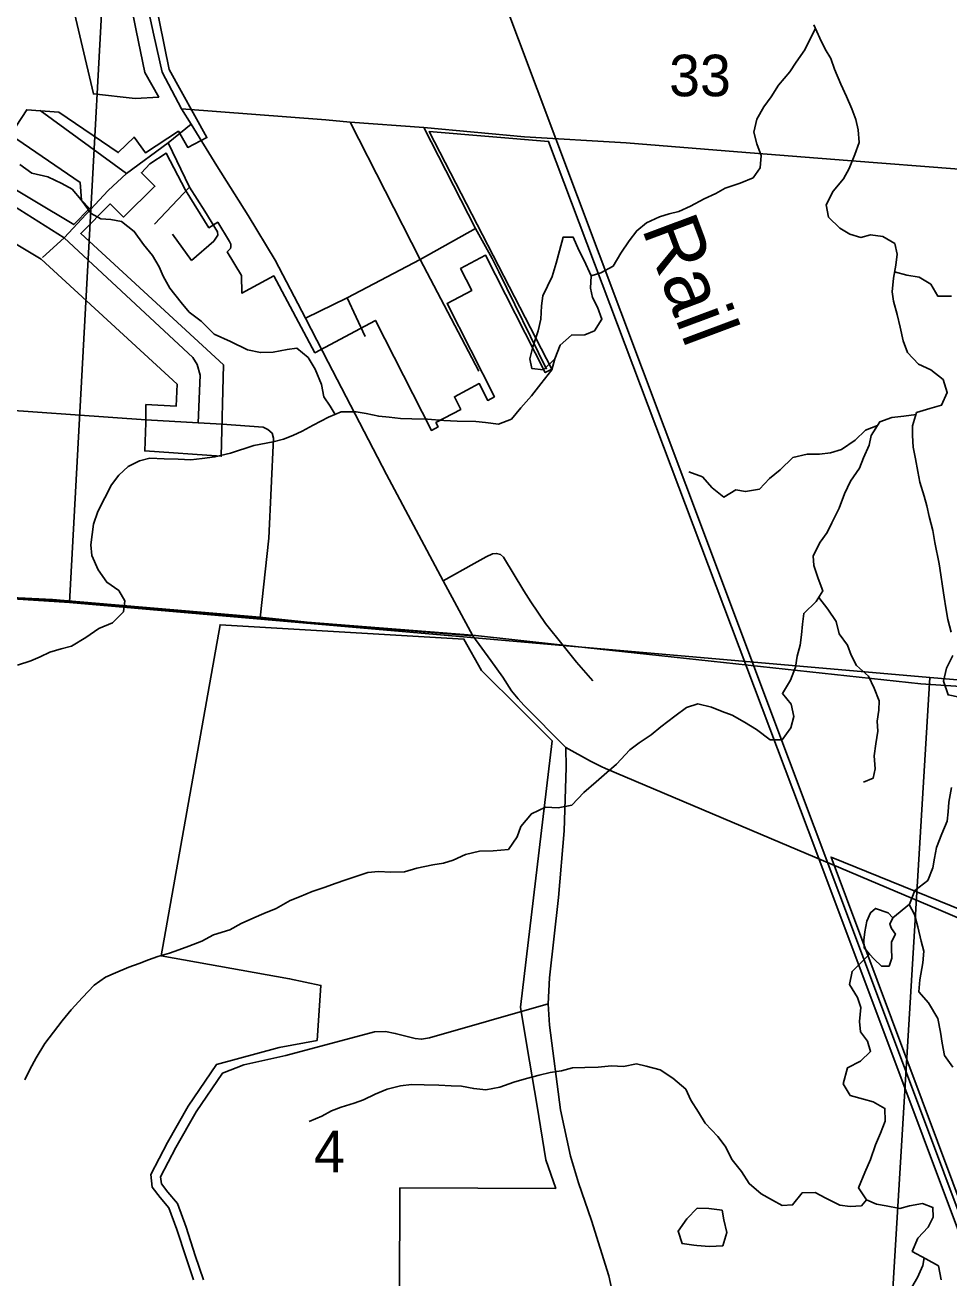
# Model space of a CAD drawing. Extents: x 0 to 34, y 0 to 22.
# Drawn here: x 28.447 to 29.378, y 19.082 to 20.344 of the extents above; entities that cross this region are included whole.
import ezdxf

# ---------------------------------------------------------------- set-up
doc = ezdxf.new("R2010")
doc.units = 0
for name, color, linetype in [('GM_X_City_Street', 7, 'Continuous'), ('GM_X_Corporation', 7, 'Continuous'), ('GM_X_County_Road', 7, 'Continuous'), ('GM_X_Major_River', 7, 'Continuous'), ('GM_X_Minor_Lake', 7, 'Continuous'), ('GM_X_Minor_River', 7, 'Continuous'), ('GM_X_Rail_Line', 7, 'Continuous'), ('GM_X_Rail_Line_Text', 7, 'Continuous'), ('GM_X_Section_Text', 7, 'Continuous'), ('GM_X_State_Route', 7, 'Continuous'), ('GM_X_Township_Road', 7, 'Continuous')]:
    doc.layers.add(name, color=color, linetype=linetype)

msp = doc.modelspace()

# ---------------------------------------------------------------- linework, layer by layer
at = {"layer": 'GM_X_City_Street'}
msp.add_line((28.5492, 20.1947), (28.4619, 20.2581), dxfattribs=at)
for points in [[(28.95, 20.2316), (29.0526, 20.2256), (29.1647, 20.2167), (29.2757, 20.2079), (29.3882, 20.1992), (29.48, 20.1917), (29.5875, 20.1831), (29.6516, 20.1783), (29.6584, 20.1781), (29.6681, 20.179), (29.6791, 20.1815), (29.6912, 20.1852), (29.7063, 20.1906), (29.722, 20.1978), (29.7365, 20.205), (29.7592, 20.2196), (29.858, 20.3004), (29.8857, 20.3208), (29.9177, 20.3417)], [(28.6046, 20.2598), (28.75, 20.2489), (28.7745, 20.2466), (28.8485, 20.2411), (28.95, 20.2316)], [(28.4643, 20.1103), (28.4861, 20.1301), (28.5307, 20.1776), (28.5492, 20.1947), (28.5909, 20.2256), (28.6141, 20.2445)], [(28.6211, 19.9437), (28.6231, 19.9918), (28.6203, 20.0024), (28.616, 20.0095), (28.4861, 20.1301), (28.4414, 20.1581), (28.3821, 20.195), (28.3757, 20.1985), (28.3672, 20.2006), (28.3594, 20.2017), (28.3263, 20.2006), (28.2805, 20.1982), (28.2717, 20.1938), (28.2616, 20.1834)], [(28.5684, 19.9468), (28.6211, 19.9437), (28.6455, 19.9423)], [(28.6265, 19.0804), (28.6183, 19.1051), (28.609, 19.1336), (28.6004, 19.1572), (28.5906, 19.1686), (28.5842, 19.177), (28.5834, 19.1842), (28.5987, 19.2137), (28.6194, 19.2497), (28.6457, 19.2887), (28.6674, 19.297), (28.7097, 19.3065), (28.7991, 19.3301), (28.8101, 19.3304), (28.8199, 19.3287), (28.84, 19.3234), (28.8464, 19.3227), (28.8545, 19.3241), (28.9739, 19.3586)]]:
    msp.add_lwpolyline(points, dxfattribs=at)
at = {"layer": 'GM_X_Corporation'}
for points in [[(27.713, 19.8126), (27.7479, 19.8098), (27.921, 19.7976), (28.0078, 19.7898), (28.15, 19.7813), (28.3845, 19.7702), (28.4743, 19.7657), (28.6835, 19.7478), (28.7311, 19.743), (28.8977, 19.7297), (28.9889, 19.7198), (29.3495, 19.6807), (29.4353, 19.675), (29.5232, 19.6666), (30.3167, 19.5906), (30.3167, 20.9), (26.3743, 20.9)], [(28.5483, 20.5152), (28.5921, 20.2996), (28.6301, 20.2309), (28.6107, 20.221), (28.6014, 20.2373), (28.5683, 20.2156), (28.5566, 20.2315), (28.5407, 20.2158), (28.481, 20.2565), (28.4486, 20.259), (28.4322, 20.2339), (28.5023, 20.1858), (28.5036, 20.168), (28.5118, 20.1596), (28.4959, 20.1434), (28.3709, 20.2181)], [(28.5435, 20.4146), (28.5589, 20.339), (28.5675, 20.2966), (28.5816, 20.2718), (28.5577, 20.2705), (28.5157, 20.2749), (28.4908, 20.3808)], [(28.3604, 20.1698), (28.4629, 20.1086), (28.6001, 19.9826), (28.599, 19.9604), (28.5686, 19.9621), (28.5686, 19.9435), (28.5681, 19.9342), (28.5675, 19.9154), (28.6445, 19.91), (28.6468, 20.002), (28.503, 20.1343), (28.5325, 20.1642), (28.5461, 20.1509), (28.5776, 20.1819), (28.5641, 20.1955), (28.5727, 20.2045), (28.5889, 20.2153), (28.6086, 20.1781), (28.6321, 20.1401), (28.641, 20.1457), (28.6527, 20.1264), (28.6534, 20.1251), (28.654, 20.1237), (28.6543, 20.1225), (28.6542, 20.121), (28.6538, 20.1193), (28.6506, 20.1159), (28.6649, 20.0921), (28.6652, 20.0744), (28.6974, 20.0917), (28.7389, 20.0143), (28.7999, 20.0468), (28.8563, 19.9361), (28.863, 19.9396), (28.8608, 19.9439), (28.8859, 19.9572), (28.8795, 19.9699), (28.9045, 19.9832), (28.9131, 19.9663), (28.9198, 19.9699), (28.872, 20.0639), (28.8969, 20.077), (28.8857, 20.099), (28.9108, 20.1124), (28.971, 19.9942), (28.9777, 19.9978), (28.8541, 20.2372), (28.9744, 20.2272), (29.2436, 19.5128), (29.5681, 18.6478)], [(30.3167, 14.1), (30.3167, 19.5906), (29.5232, 19.6666), (29.4353, 19.675), (29.3495, 19.6807), (28.9889, 19.7198), (28.8977, 19.7297), (28.7311, 19.743), (28.6835, 19.7478), (28.4743, 19.7657), (28.3845, 19.7702), (28.15, 19.7813), (28.0078, 19.7898), (27.921, 19.7976), (27.7479, 19.8098), (27.713, 19.8126)], [(28.6165, 19.0805), (28.6091, 19.1027), (28.5998, 19.131), (28.5918, 19.1529), (28.583, 19.1632), (28.5748, 19.1739), (28.5735, 19.1866), (28.5902, 19.2188), (28.6111, 19.2552), (28.6396, 19.2974), (28.7029, 19.3145), (28.741, 19.3215), (28.745, 19.3769), (28.7133, 19.3837), (28.5841, 19.4067), (28.6433, 19.7402), (28.8891, 19.7259), (28.9068, 19.6942), (28.946, 19.6553), (28.9781, 19.6233), (28.9461, 19.3551), (28.9525, 19.3164), (28.963, 19.2554), (28.9716, 19.2012), (28.9816, 19.1725), (28.8245, 19.173), (28.8221, 18.423)], [(29.5806, 18.6469), (29.2591, 19.5062), (29.4529, 19.4276)]]:
    msp.add_lwpolyline(points, dxfattribs=at)
for points in [[(27.5018, 20.8365), (28.5465, 20.7695), (28.4917, 19.7627), (28.3876, 19.7694), (27.4311, 19.8373)], [(28.5465, 20.7695), (29.5293, 20.6826), (29.4415, 19.6802), (29.3585, 19.6871), (28.4917, 19.7627)], [(28.4917, 19.7627), (29.3585, 19.6871), (29.2972, 18.6715), (28.6566, 18.7331), (28.2889, 18.7562), (28.3876, 19.7694)], [(30.3167, 18.7853), (30.3167, 19.5984), (29.4415, 19.6802), (29.3585, 19.6871), (29.2972, 18.6715), (30.2969, 18.5954)]]:
    msp.add_lwpolyline(points, close=True, dxfattribs=at)
at = {"layer": 'GM_X_County_Road'}
msp.add_lwpolyline([(29.0546, 18.9586), (29.0544, 18.9674), (29.0538, 18.9872), (29.0494, 19.018), (29.0351, 19.0845), (29.0176, 19.1401), (29.0044, 19.1782), (28.9965, 19.2049), (28.9863, 19.2516), (28.9753, 19.3368), (28.9739, 19.3586), (28.9753, 19.3846), (28.9842, 19.4654), (28.99, 19.5328), (28.9921, 19.5966), (28.9916, 19.6165)], dxfattribs=at)
at = {"layer": 'GM_X_Major_River'}
for points in [[(29.2417, 20.3445), (29.2476, 20.3312), (29.2532, 20.3201), (29.2588, 20.3106), (29.2625, 20.2999), (29.2688, 20.2847), (29.2744, 20.2725), (29.28, 20.26), (29.2841, 20.2493), (29.2862, 20.2387), (29.2873, 20.2261), (29.283, 20.214), (29.2772, 20.2), (29.2714, 20.1895), (29.2611, 20.177), (29.2542, 20.1634), (29.2563, 20.1509), (29.268, 20.1398), (29.2778, 20.1336), (29.2891, 20.1305), (29.2986, 20.1331), (29.3111, 20.1315), (29.3232, 20.1242), (29.3257, 20.1135), (29.3241, 20.1025), (29.3218, 20.0893), (29.3205, 20.0756), (29.3219, 20.0661), (29.3256, 20.0528), (29.3285, 20.0399), (29.3318, 20.0262), (29.3359, 20.0144), (29.3472, 20.0029), (29.3596, 19.9972), (29.3721, 19.9872), (29.3761, 19.9743), (29.3703, 19.9614), (29.3585, 19.9581), (29.3452, 19.954), (29.341, 19.9408), (29.3409, 19.9309), (29.3419, 19.9191), (29.3441, 19.9073), (29.3463, 19.8948), (29.3484, 19.8838), (29.3529, 19.8697), (29.3554, 19.8602), (29.358, 19.8492), (29.3617, 19.8351), (29.3635, 19.823), (29.3678, 19.8017), (29.3696, 19.7907), (29.3714, 19.7793), (29.3729, 19.7679), (29.3747, 19.7572), (29.3768, 19.7455), (29.3801, 19.7329)], [(29.3818, 19.7094), (29.3753, 19.6965), (29.3722, 19.6833), (29.377, 19.6696), (29.3883, 19.6672)], [(29.3803, 19.5762), (29.3776, 19.5614), (29.3771, 19.5519), (29.3759, 19.5425), (29.3705, 19.5296), (29.3651, 19.516), (29.3631, 19.505), (29.3615, 19.4955), (29.3564, 19.4827), (29.3435, 19.4725), (29.338, 19.4589), (29.3213, 19.445)], [(29.3164, 19.45), (29.3039, 19.4546), (29.2986, 19.4501), (29.2951, 19.4418), (29.2931, 19.4308), (29.2919, 19.4225), (29.2922, 19.4149), (29.2978, 19.4084)], [(29.3164, 19.45), (29.3039, 19.4546), (29.2986, 19.4501), (29.2951, 19.4418), (29.2931, 19.4308), (29.2919, 19.4225), (29.2922, 19.4149), (29.2978, 19.4084), (29.3023, 19.4034), (29.3099, 19.3965), (29.3174, 19.3965), (29.3202, 19.4044), (29.3199, 19.4143), (29.3199, 19.4207), (29.3222, 19.4256), (29.3238, 19.4287), (29.32, 19.4344), (29.3182, 19.4386), (29.3213, 19.445)], [(29.3213, 19.445), (29.3164, 19.45)], [(29.2978, 19.4084), (29.3023, 19.4034), (29.3099, 19.3965), (29.3174, 19.3965), (29.3202, 19.4044), (29.3199, 19.4143), (29.3199, 19.4207), (29.3222, 19.4256), (29.3238, 19.4287), (29.32, 19.4344), (29.3182, 19.4386), (29.3213, 19.445)], [(29.2978, 19.4084), (29.2802, 19.3911), (29.2775, 19.3778), (29.2857, 19.3648), (29.289, 19.3546), (29.2878, 19.3405), (29.2885, 19.3303), (29.2956, 19.3208), (29.2989, 19.3105), (29.2886, 19.3007), (29.2756, 19.294), (29.2713, 19.2777), (29.2784, 19.2662), (29.2917, 19.2624), (29.3015, 19.2596), (29.3132, 19.2531), (29.3135, 19.2402), (29.3088, 19.2281), (29.3038, 19.2163), (29.2987, 19.2016), (29.2929, 19.1884), (29.2868, 19.1732), (29.2946, 19.161), (29.3048, 19.1568), (29.3146, 19.1548), (29.3283, 19.1524), (29.3381, 19.155), (29.351, 19.1572), (29.3616, 19.1533), (29.3619, 19.1434), (29.3569, 19.1336), (29.3466, 19.1223), (29.3408, 19.1091), (29.3544, 19.1017), (29.3672, 19.0944), (29.3701, 19.0804)]]:
    msp.add_lwpolyline(points, dxfattribs=at)
at = {"layer": 'GM_X_Minor_Lake'}
for points in [[(29.0173, 20.0918), (29.0101, 20.107), (29.0049, 20.1176), (28.9992, 20.1306), (28.989, 20.1306), (28.9852, 20.1169), (28.9821, 20.1044), (28.9779, 20.0912), (28.9733, 20.0813), (28.9684, 20.0715), (28.9672, 20.0616), (28.9664, 20.048), (28.9637, 20.0362), (28.9584, 20.0203), (28.9553, 20.0082), (28.9575, 19.9983), (28.9693, 19.9972), (28.9807, 20.0081)], [(28.9807, 20.0081), (28.986, 20.0218), (28.9974, 20.032), (29.011, 20.0323), (29.0205, 20.0364), (29.0281, 20.0482), (29.0236, 20.0603), (29.0187, 20.0698), (29.0165, 20.0793), (29.0173, 20.0918)], [(29.1492, 19.1505), (29.1359, 19.1524), (29.1242, 19.1525), (29.1136, 19.1419), (29.1048, 19.1294), (29.1089, 19.1169), (29.1207, 19.1153)], [(29.1207, 19.1153), (29.1237, 19.1149), (29.1366, 19.1141), (29.1498, 19.1148), (29.154, 19.1281), (29.151, 19.141), (29.1492, 19.1505)]]:
    msp.add_lwpolyline(points, dxfattribs=at)
at = {"layer": 'GM_X_Minor_River'}
for points in [[(29.2434, 20.3407), (29.2372, 20.3292), (29.2326, 20.3194), (29.2239, 20.3069), (29.2174, 20.2971), (29.206, 20.2838), (29.1988, 20.2721), (29.1912, 20.2619), (29.1843, 20.2494), (29.1813, 20.2365), (29.1843, 20.2247), (29.1884, 20.213), (29.1876, 20.2005), (29.1804, 20.1906), (29.1675, 20.185), (29.1523, 20.1801), (29.1428, 20.1748), (29.1311, 20.1692), (29.1174, 20.162), (29.1057, 20.1564), (29.0958, 20.1541), (29.086, 20.1511), (29.0731, 20.1451), (29.0632, 20.1372), (29.0556, 20.127), (29.0473, 20.1145), (29.0393, 20.1016), (29.0271, 20.0948), (29.0173, 20.0918), (29.0165, 20.0793), (29.0187, 20.0698), (29.0236, 20.0603), (29.0281, 20.0482), (29.0205, 20.0364), (29.011, 20.0323), (28.9974, 20.032), (28.986, 20.0218), (28.9807, 20.0081), (28.9776, 19.9971), (28.9666, 19.9831), (28.9571, 19.9707), (28.9464, 19.9589), (28.9369, 19.9472), (28.924, 19.9423), (28.9108, 19.9439), (28.901, 19.9451), (28.8821, 19.9455), (28.8688, 19.9459), (28.8522, 19.9475), (28.8366, 19.9476), (28.8253, 19.948), (28.8136, 19.9492), (28.8033, 19.9503), (28.7905, 19.953), (28.7803, 19.9546), (28.7655, 19.9546), (28.7526, 19.9494), (28.7371, 19.9414), (28.7261, 19.9354), (28.7166, 19.9309), (28.7071, 19.9271), (28.6969, 19.9245), (28.6772, 19.9208), (28.6537, 19.9131)], [(28.6538, 20.0257), (28.6375, 20.033), (28.6244, 20.046), (28.6123, 20.0552), (28.6041, 20.0647), (28.5928, 20.0792), (28.5861, 20.0914), (28.582, 20.1009), (28.5753, 20.1123), (28.5663, 20.1234), (28.5569, 20.1364), (28.5441, 20.1463), (28.5331, 20.1483), (28.5233, 20.1491), (28.5135, 20.1545), (28.5034, 20.1682), (28.4944, 20.1789), (28.4838, 20.1846), (28.4699, 20.1916), (28.4536, 20.1951), (28.4416, 20.2039)], [(29.3229, 20.0956), (29.3352, 20.0923), (29.3477, 20.0903), (29.3594, 20.0834), (29.3665, 20.0713), (29.3802, 20.0712)], [(28.7593, 19.9521), (28.7542, 19.9604), (28.7478, 19.9699), (28.7456, 19.9824), (28.7392, 19.9976), (28.732, 20.0093), (28.7207, 20.0189), (28.7109, 20.0174), (28.6968, 20.0148), (28.684, 20.0144), (28.6711, 20.0171), (28.6538, 20.0257)], [(29.3446, 19.9519), (29.3324, 19.9504), (29.3203, 19.949), (29.3082, 19.9448), (29.2994, 19.9308), (29.2975, 19.9213), (29.2918, 19.9085), (29.2876, 19.8979), (29.2785, 19.885), (29.2727, 19.8721), (29.267, 19.8577), (29.2598, 19.843), (29.2552, 19.8331), (29.248, 19.8233), (29.2411, 19.8097), (29.2415, 19.7998), (29.246, 19.7869), (29.2508, 19.7744), (29.244, 19.7638), (29.2315, 19.7517), (29.2303, 19.7407), (29.2291, 19.7301), (29.2279, 19.7198), (29.2249, 19.7085), (29.223, 19.6975), (29.218, 19.6846), (29.21, 19.671), (29.2187, 19.6603), (29.2216, 19.6478), (29.2186, 19.6364), (29.2098, 19.6243), (29.1977, 19.6244), (29.1838, 19.6347), (29.1717, 19.6423), (29.1592, 19.6492), (29.1494, 19.653), (29.1384, 19.6572), (29.1248, 19.6606), (29.1134, 19.6569), (29.1017, 19.6482), (29.0876, 19.6376), (29.0778, 19.6293), (29.0656, 19.6214), (29.0561, 19.6142), (29.0428, 19.5999), (29.033, 19.5916), (29.0223, 19.5821), (29.0098, 19.5712), (28.9977, 19.5587), (28.984, 19.5557), (28.9712, 19.5565), (28.9571, 19.5497), (28.9465, 19.5369), (28.9427, 19.5266), (28.9339, 19.5138), (28.9184, 19.5127), (28.9048, 19.5123), (28.8908, 19.509), (28.8783, 19.5033), (28.8684, 19.5), (28.8578, 19.4985), (28.8415, 19.4951), (28.829, 19.4914), (28.8154, 19.491), (28.8029, 19.4918), (28.7923, 19.4907), (28.7813, 19.487), (28.77, 19.4832), (28.7593, 19.4798), (28.7491, 19.4761), (28.7362, 19.4716), (28.7233, 19.4663), (28.7139, 19.4626), (28.6998, 19.4543), (28.6873, 19.4494), (28.6775, 19.4452), (28.6646, 19.4392), (28.653, 19.433)], [(29.3057, 19.9409), (29.2938, 19.9362), (29.2832, 19.9263), (29.2695, 19.9169), (29.2585, 19.9135), (29.2475, 19.912), (29.235, 19.9121), (29.2206, 19.9087), (29.2077, 19.8962), (29.1971, 19.8876), (29.1869, 19.877), (29.1728, 19.8744), (29.163, 19.8763), (29.1509, 19.8688), (29.1392, 19.8783), (29.1294, 19.8893), (29.1158, 19.8943)], [(28.6537, 19.9131), (28.6382, 19.9094), (28.6253, 19.9076), (28.614, 19.9065), (28.6011, 19.907), (28.5871, 19.9075), (28.5727, 19.9079), (28.5621, 19.9054), (28.5507, 19.8997), (28.5412, 19.8911), (28.534, 19.8813), (28.5271, 19.868), (28.5202, 19.8544), (28.5159, 19.8416), (28.5143, 19.8313), (28.5131, 19.8207), (28.5142, 19.8101), (28.5205, 19.7957), (28.5291, 19.7831), (28.5412, 19.7747), (28.5472, 19.7644), (28.546, 19.7534), (28.5349, 19.7421), (28.5212, 19.7365), (28.5079, 19.7275), (28.4935, 19.7188), (28.4833, 19.7159), (28.4719, 19.7125), (28.462, 19.7081), (28.4525, 19.7039), (28.4393, 19.6995)], [(29.2466, 19.7678), (29.2557, 19.7561), (29.264, 19.7436), (29.2673, 19.7311), (29.2756, 19.7197), (29.2794, 19.7098), (29.2846, 19.6992), (29.2967, 19.6885), (29.3024, 19.6763), (29.3076, 19.6638), (29.3072, 19.6543), (29.3056, 19.643), (29.306, 19.6331), (29.3041, 19.6202), (29.3025, 19.6081), (29.3036, 19.5952), (29.3013, 19.5857), (29.2918, 19.5816)], [(29.3377, 19.4586), (29.3432, 19.4483), (29.3466, 19.4361), (29.3499, 19.4217), (29.3525, 19.4115), (29.3514, 19.3997), (29.3483, 19.3827), (29.3475, 19.3705), (29.3573, 19.3595), (29.3667, 19.3435), (29.3693, 19.3299), (29.3708, 19.3189), (29.3734, 19.3064), (29.3817, 19.2946)], [(28.653, 19.433), (28.6368, 19.4281), (28.625, 19.4214), (28.6118, 19.4165), (28.6019, 19.4128), (28.5924, 19.4095), (28.5807, 19.4061), (28.5712, 19.4028), (28.5617, 19.399), (28.5515, 19.3953), (28.5378, 19.3897), (28.5279, 19.3852), (28.5165, 19.3773), (28.5047, 19.3649), (28.4933, 19.3525), (28.4841, 19.3412), (28.4669, 19.3185), (28.4581, 19.3042), (28.4516, 19.2924), (28.4466, 19.2819)], [(29.2946, 19.161), (29.2896, 19.155), (29.2782, 19.1542), (29.268, 19.1558), (29.2537, 19.1627), (29.2431, 19.1684), (29.2298, 19.168), (29.2203, 19.1559), (29.2097, 19.1552), (29.1999, 19.1606), (29.1886, 19.1671), (29.1765, 19.1773), (29.1686, 19.1895), (29.1592, 19.2013), (29.1524, 19.215), (29.1449, 19.2248), (29.1321, 19.2382), (29.1253, 19.2492), (29.1178, 19.2613), (29.1125, 19.2724), (29.0997, 19.2834), (29.0868, 19.2918), (29.0728, 19.2956), (29.063, 19.2979), (29.0497, 19.2953), (29.0376, 19.2961), (29.0244, 19.2946), (29.0108, 19.2943), (28.9983, 19.294), (28.9873, 19.291), (28.9759, 19.2891), (28.9649, 19.2865), (28.9521, 19.2831), (28.9392, 19.2794), (28.9252, 19.2745), (28.9112, 19.2719), (28.899, 19.2731), (28.8866, 19.2754), (28.8763, 19.2758), (28.8639, 19.2766), (28.8491, 19.277), (28.8362, 19.2771), (28.8253, 19.276), (28.8116, 19.2726), (28.7995, 19.2673), (28.7877, 19.2617), (28.7783, 19.2583), (28.7654, 19.2542), (28.7555, 19.2508), (28.7457, 19.2452), (28.7332, 19.2399)], [(29.3528, 19.1026), (29.3515, 19.0948), (29.3461, 19.0827), (29.3381, 19.0691)]]:
    msp.add_lwpolyline(points, dxfattribs=at)
at = {"layer": 'GM_X_Rail_Line'}
for points in [[(29.1913, 19.6716), (29.1345, 19.823), (28.9817, 20.2298), (28.8105, 20.6857), (28.73, 20.9)], [(29.4527, 18.9755), (29.2926, 19.4017), (29.1913, 19.6716)]]:
    msp.add_lwpolyline(points, dxfattribs=at)
at = {"layer": 'GM_X_State_Route'}
msp.add_line((28.5767, 20.3343), (28.5439, 20.4822), dxfattribs=at)
for points in [[(28.6402, 20.2026), (28.6141, 20.2445), (28.6046, 20.2598), (28.5851, 20.2969), (28.5767, 20.3343)], [(28.7524, 20.0048), (28.7295, 20.049), (28.699, 20.1074), (28.6715, 20.1524), (28.6402, 20.2026)], [(28.8979, 19.7292), (28.8682, 19.7846), (28.811, 19.8915), (28.7524, 20.0048)], [(28.9438, 19.6658), (28.9371, 19.6738), (28.9281, 19.6875), (28.9162, 19.7041), (28.8979, 19.7292)], [(29.0273, 19.5976), (29.0166, 19.6027), (28.9916, 19.6165), (28.9493, 19.6592), (28.9438, 19.6658)], [(29.4998, 19.3943), (29.4097, 19.4354), (29.3673, 19.4536), (29.2078, 19.5211), (29.0317, 19.5955), (29.0273, 19.5976)]]:
    msp.add_lwpolyline(points, dxfattribs=at)
at = {"layer": 'GM_X_Township_Road'}
for p, q in [((28.5771, 20.1438), (28.6126, 20.1809)), ((28.5954, 20.1338), (28.6146, 20.1073)), ((28.9723, 19.9978), (28.9242, 20.0956)), ((28.7715, 20.0697), (28.7896, 20.0305))]:
    msp.add_line(p, q, dxfattribs=at)
for points in [[(28.904, 19.9958), (28.845, 20.1083), (28.7745, 20.2466)], [(28.9242, 20.0956), (28.9174, 20.1093), (28.9008, 20.1393), (28.8485, 20.2411)], [(28.6278, 20.1568), (28.6126, 20.1809), (28.5909, 20.2256)], [(28.6146, 20.1073), (28.6372, 20.1267), (28.6412, 20.1326), (28.6408, 20.1359), (28.6278, 20.1568)], [(28.7295, 20.049), (28.7715, 20.0697), (28.845, 20.1083), (28.9008, 20.1393)], [(28.5684, 19.9468), (28.3877, 19.9595), (28.2855, 19.9623)], [(28.6838, 19.7473), (28.6925, 19.8276), (28.6972, 19.9281), (28.6958, 19.9331), (28.6914, 19.9371), (28.6869, 19.9393), (28.6455, 19.9423)], [(28.8682, 19.7846), (28.8992, 19.8018), (28.9116, 19.8088), (28.9179, 19.8118), (28.922, 19.8121), (28.926, 19.811), (28.929, 19.8084), (28.9493, 19.7744), (28.9566, 19.7634)], [(27.9222, 19.797), (28.008, 19.7893), (28.1502, 19.7808), (28.3847, 19.7696), (28.4745, 19.7652), (28.6838, 19.7473), (28.7313, 19.7425), (28.8979, 19.7292)], [(28.9566, 19.7634), (28.9712, 19.7415), (28.9891, 19.7193), (29.0026, 19.7026), (29.0189, 19.6838)]]:
    msp.add_lwpolyline(points, dxfattribs=at)

# ---------------------------------------------------------------- texts
at = {"layer": 'GM_X_Rail_Line_Text'}
msp.add_text('Rail', height=0.05663, rotation=290.4835, dxfattribs=at).set_placement((29.0679, 20.1395))
at = {"layer": 'GM_X_Section_Text'}
for s, height, p in [('33', 0.04186, (29.0958, 20.2726)), ('4', 0.0419, (28.7379, 19.1888))]:
    msp.add_text(s, height=height, rotation=0, dxfattribs=at).set_placement(p)

doc.saveas('drawing.dxf')
